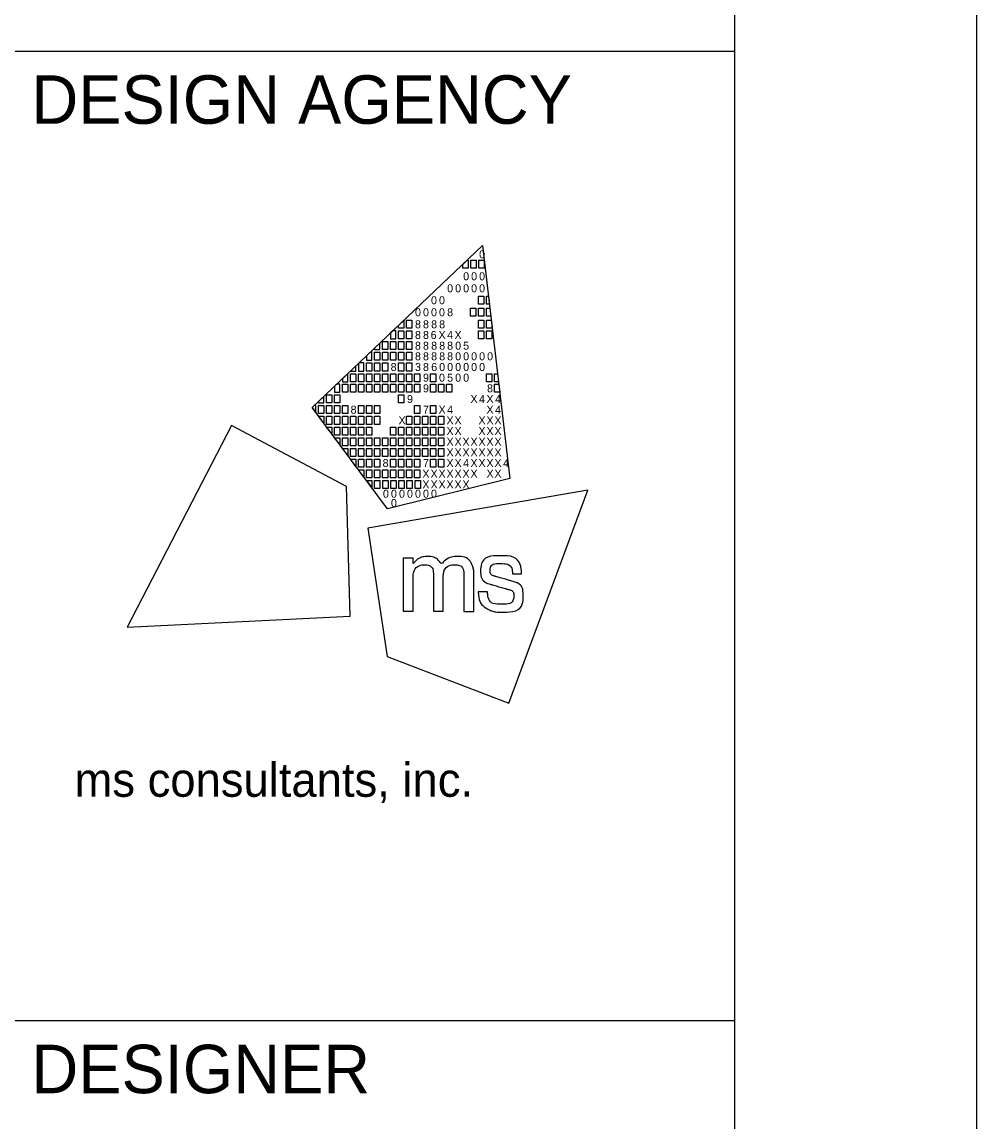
# Model space of a CAD drawing. Extents: x -0.2 to 33.8, y 0.1 to 22.1.
# Drawn here: x 31.828 to 33.798, y 2.411 to 4.681 of the extents above; entities that cross this region are included whole.
import ezdxf

# ---------------------------------------------------------------- set-up
doc = ezdxf.new("R2010")
doc.units = 0
for name, color, linetype in [('Default', 7, 'Continuous'), ('SH_Border', 7, 'Continuous'), ('SH_Cut_Line', 7, 'Continuous'), ('SH_Data', 7, 'Continuous')]:
    doc.layers.add(name, color=color, linetype=linetype)

msp = doc.modelspace()

# ---------------------------------------------------------------- linework, layer by layer
at = {"layer": 'Default'}
for p, q in [((32.4267, 3.8854), (32.778, 4.2196)), ((32.778, 4.2196), (32.778, 4.2196)), ((32.778, 4.2196), (32.8345, 3.7387)), ((32.5822, 3.6765), (32.4267, 3.8854)), ((32.8345, 3.7387), (32.5822, 3.6765))]:
    msp.add_line(p, q, dxfattribs=at)
for points in [[(32.7371, 4.1807), (32.7461, 4.1893), (32.7481, 4.1893), (32.7481, 4.1728), (32.7371, 4.1728)], [(32.7536, 4.1893), (32.7646, 4.1893), (32.7646, 4.1728), (32.7536, 4.1728)], [(32.7701, 4.1893), (32.7811, 4.1893), (32.7811, 4.1728), (32.7701, 4.1728)], [(32.7698, 4.115), (32.7808, 4.115), (32.7808, 4.0985), (32.7698, 4.0985)], [(32.7863, 4.115), (32.7903, 4.115), (32.7922, 4.0985), (32.7863, 4.0985)], [(32.7533, 4.0902), (32.7643, 4.0902), (32.7643, 4.0737), (32.7533, 4.0737)], [(32.7698, 4.0902), (32.7808, 4.0902), (32.7808, 4.0737), (32.7698, 4.0737)], [(32.7863, 4.0902), (32.7932, 4.0902), (32.7951, 4.0737), (32.7863, 4.0737)], [(32.6045, 4.0546), (32.6156, 4.0651), (32.6156, 4.0489), (32.6045, 4.0489)], [(32.6215, 4.0654), (32.6325, 4.0654), (32.6325, 4.0489), (32.6215, 4.0489)], [(32.7698, 4.0654), (32.7808, 4.0654), (32.7808, 4.0489), (32.7698, 4.0489)], [(32.7863, 4.0654), (32.7961, 4.0654), (32.7973, 4.0553), (32.7973, 4.0489), (32.7863, 4.0489)], [(32.605, 4.0434), (32.616, 4.0434), (32.616, 4.0269), (32.605, 4.0269)], [(32.6215, 4.0434), (32.6325, 4.0434), (32.6325, 4.0269), (32.6215, 4.0269)], [(32.7698, 4.0434), (32.7808, 4.0434), (32.7808, 4.0269), (32.7698, 4.0269)], [(32.7863, 4.0434), (32.7973, 4.0434), (32.7973, 4.0269), (32.7863, 4.0269)], [(32.5719, 4.0214), (32.5829, 4.0214), (32.5829, 4.0049), (32.5719, 4.0049)], [(32.5885, 4.0214), (32.5995, 4.0214), (32.5995, 4.0049), (32.5885, 4.0049)], [(32.605, 4.0214), (32.616, 4.0214), (32.616, 4.0049), (32.605, 4.0049)], [(32.6215, 4.0214), (32.6325, 4.0214), (32.6325, 4.0049), (32.6215, 4.0049)], [(32.5554, 3.9994), (32.5664, 3.9994), (32.5664, 3.9829), (32.5554, 3.9829)], [(32.5719, 3.9994), (32.5829, 3.9994), (32.5829, 3.9829), (32.5719, 3.9829)], [(32.5885, 3.9994), (32.5995, 3.9994), (32.5995, 3.9829), (32.5885, 3.9829)], [(32.605, 3.9994), (32.616, 3.9994), (32.616, 3.9829), (32.605, 3.9829)], [(32.6215, 3.9994), (32.6325, 3.9994), (32.6325, 3.9829), (32.6215, 3.9829)], [(32.5389, 3.9774), (32.5499, 3.9774), (32.5499, 3.9608), (32.5389, 3.9608)], [(32.5554, 3.9774), (32.5664, 3.9774), (32.5664, 3.9608), (32.5554, 3.9608)], [(32.5719, 3.9774), (32.5829, 3.9774), (32.5829, 3.9608), (32.5719, 3.9608)], [(32.605, 3.9774), (32.616, 3.9774), (32.616, 3.9608), (32.605, 3.9608)], [(32.6215, 3.9774), (32.6325, 3.9774), (32.6325, 3.9608), (32.6215, 3.9608)], [(32.5059, 3.9553), (32.5169, 3.9553), (32.5169, 3.9388), (32.5059, 3.9388)], [(32.5224, 3.9553), (32.5334, 3.9553), (32.5334, 3.9388), (32.5224, 3.9388)], [(32.5389, 3.9553), (32.5499, 3.9553), (32.5499, 3.9388), (32.5389, 3.9388)], [(32.5554, 3.9553), (32.5664, 3.9553), (32.5664, 3.9388), (32.5554, 3.9388)], [(32.5719, 3.9553), (32.5829, 3.9553), (32.5829, 3.9388), (32.5719, 3.9388)], [(32.5885, 3.9553), (32.5995, 3.9553), (32.5995, 3.9388), (32.5885, 3.9388)], [(32.605, 3.9553), (32.616, 3.9553), (32.616, 3.9388), (32.605, 3.9388)], [(32.6215, 3.9553), (32.6325, 3.9553), (32.6325, 3.9388), (32.6215, 3.9388)], [(32.638, 3.9553), (32.649, 3.9553), (32.649, 3.9388), (32.638, 3.9388)], [(32.671, 3.9553), (32.682, 3.9553), (32.682, 3.9388), (32.671, 3.9388)], [(32.7863, 3.9553), (32.7973, 3.9553), (32.7973, 3.9388), (32.7863, 3.9388)], [(32.8027, 3.9553), (32.809, 3.9553), (32.811, 3.9388), (32.8027, 3.9388)], [(32.4894, 3.9333), (32.5004, 3.9333), (32.5004, 3.9168), (32.4894, 3.9168)], [(32.5059, 3.9333), (32.5169, 3.9333), (32.5169, 3.9168), (32.5059, 3.9168)], [(32.5224, 3.9333), (32.5334, 3.9333), (32.5334, 3.9168), (32.5224, 3.9168)], [(32.5389, 3.9333), (32.5499, 3.9333), (32.5499, 3.9168), (32.5389, 3.9168)], [(32.5554, 3.9333), (32.5664, 3.9333), (32.5664, 3.9168), (32.5554, 3.9168)], [(32.5719, 3.9333), (32.5829, 3.9333), (32.5829, 3.9168), (32.5719, 3.9168)], [(32.5885, 3.9333), (32.5995, 3.9333), (32.5995, 3.9168), (32.5885, 3.9168)], [(32.605, 3.9333), (32.616, 3.9333), (32.616, 3.9168), (32.605, 3.9168)], [(32.6215, 3.9333), (32.6325, 3.9333), (32.6325, 3.9168), (32.6215, 3.9168)], [(32.638, 3.9333), (32.649, 3.9333), (32.649, 3.9168), (32.638, 3.9168)], [(32.671, 3.9333), (32.682, 3.9333), (32.682, 3.9168), (32.671, 3.9168)], [(32.6875, 3.9333), (32.6985, 3.9333), (32.6985, 3.9168), (32.6875, 3.9168)], [(32.7039, 3.9333), (32.7149, 3.9333), (32.7149, 3.9168), (32.7039, 3.9168)], [(32.8027, 3.9333), (32.8116, 3.9333), (32.8136, 3.9168), (32.8027, 3.9168)], [(32.4563, 3.9113), (32.4674, 3.9113), (32.4674, 3.8948), (32.4563, 3.8948)], [(32.4729, 3.9113), (32.4839, 3.9113), (32.4839, 3.8948), (32.4729, 3.8948)], [(32.605, 3.9113), (32.616, 3.9113), (32.616, 3.8948), (32.605, 3.8948)], [(32.4398, 3.8893), (32.4508, 3.8893), (32.4508, 3.8728), (32.4398, 3.8728)], [(32.4563, 3.8893), (32.4674, 3.8893), (32.4674, 3.8728), (32.4563, 3.8728)], [(32.4729, 3.8893), (32.4839, 3.8893), (32.4839, 3.8728), (32.4729, 3.8728)], [(32.4894, 3.8893), (32.5004, 3.8893), (32.5004, 3.8728), (32.4894, 3.8728)], [(32.5224, 3.8893), (32.5334, 3.8893), (32.5334, 3.8728), (32.5224, 3.8728)], [(32.5389, 3.8893), (32.5499, 3.8893), (32.5499, 3.8728), (32.5389, 3.8728)], [(32.5554, 3.8893), (32.5664, 3.8893), (32.5664, 3.8728), (32.5554, 3.8728)], [(32.638, 3.8893), (32.649, 3.8893), (32.649, 3.8728), (32.638, 3.8728)], [(32.671, 3.8893), (32.682, 3.8893), (32.682, 3.8728), (32.671, 3.8728)], [(32.4398, 3.8673), (32.4508, 3.8673), (32.4508, 3.8535)], [(32.4563, 3.8673), (32.4674, 3.8673), (32.4674, 3.8507), (32.4563, 3.8507)], [(32.4729, 3.8673), (32.4839, 3.8673), (32.4839, 3.8507), (32.4729, 3.8507)], [(32.4894, 3.8673), (32.5004, 3.8673), (32.5004, 3.8507), (32.4894, 3.8507)], [(32.5059, 3.8673), (32.5169, 3.8673), (32.5169, 3.8507), (32.5059, 3.8507)], [(32.5224, 3.8673), (32.5334, 3.8673), (32.5334, 3.8507), (32.5224, 3.8507)], [(32.5389, 3.8673), (32.5499, 3.8673), (32.5499, 3.8507), (32.5389, 3.8507)], [(32.5554, 3.8673), (32.5664, 3.8673), (32.5664, 3.8507), (32.5554, 3.8507)], [(32.6215, 3.8673), (32.6325, 3.8673), (32.6325, 3.8507), (32.6215, 3.8507)], [(32.638, 3.8673), (32.649, 3.8673), (32.649, 3.8507), (32.638, 3.8507)], [(32.6545, 3.8673), (32.6655, 3.8673), (32.6655, 3.8507), (32.6545, 3.8507)], [(32.671, 3.8673), (32.682, 3.8673), (32.682, 3.8507), (32.671, 3.8507)], [(32.6875, 3.8673), (32.6985, 3.8673), (32.6985, 3.8507), (32.6875, 3.8507)], [(32.4563, 3.8452), (32.4674, 3.8452), (32.4674, 3.8315)], [(32.4729, 3.8452), (32.4839, 3.8452), (32.4839, 3.8287), (32.4729, 3.8287)], [(32.4894, 3.8452), (32.5004, 3.8452), (32.5004, 3.8287), (32.4894, 3.8287)], [(32.5059, 3.8452), (32.5169, 3.8452), (32.5169, 3.8287), (32.5059, 3.8287)], [(32.5224, 3.8452), (32.5334, 3.8452), (32.5334, 3.8287), (32.5224, 3.8287)], [(32.5389, 3.8452), (32.5499, 3.8452), (32.5499, 3.8287), (32.5389, 3.8287)], [(32.5885, 3.8452), (32.5995, 3.8452), (32.5995, 3.8287), (32.5885, 3.8287)], [(32.605, 3.8452), (32.616, 3.8452), (32.616, 3.8287), (32.605, 3.8287)], [(32.6215, 3.8452), (32.6325, 3.8452), (32.6325, 3.8287), (32.6215, 3.8287)], [(32.638, 3.8452), (32.649, 3.8452), (32.649, 3.8287), (32.638, 3.8287)], [(32.6545, 3.8452), (32.6655, 3.8452), (32.6655, 3.8287), (32.6545, 3.8287)], [(32.671, 3.8452), (32.682, 3.8452), (32.682, 3.8287), (32.671, 3.8287)], [(32.6875, 3.8452), (32.6985, 3.8452), (32.6985, 3.8287), (32.6875, 3.8287)], [(32.4729, 3.8232), (32.4839, 3.8232), (32.4839, 3.8095)], [(32.4839, 3.8232), (32.4839, 3.8232), (32.4839, 3.8232)], [(32.4894, 3.8232), (32.5004, 3.8232), (32.5004, 3.8067), (32.4894, 3.8067)], [(32.5059, 3.8232), (32.5169, 3.8232), (32.5169, 3.8067), (32.5059, 3.8067)], [(32.5224, 3.8232), (32.5334, 3.8232), (32.5334, 3.8067), (32.5224, 3.8067)], [(32.5389, 3.8232), (32.5499, 3.8232), (32.5499, 3.8067), (32.5389, 3.8067)], [(32.5554, 3.8232), (32.5664, 3.8232), (32.5664, 3.8067), (32.5554, 3.8067)], [(32.5719, 3.8232), (32.5829, 3.8232), (32.5829, 3.8067), (32.5719, 3.8067)], [(32.5885, 3.8232), (32.5995, 3.8232), (32.5995, 3.8067), (32.5885, 3.8067)], [(32.605, 3.8232), (32.616, 3.8232), (32.616, 3.8067), (32.605, 3.8067)], [(32.6215, 3.8232), (32.6325, 3.8232), (32.6325, 3.8067), (32.6215, 3.8067)], [(32.638, 3.8232), (32.649, 3.8232), (32.649, 3.8067), (32.638, 3.8067)], [(32.6545, 3.8232), (32.6655, 3.8232), (32.6655, 3.8067), (32.6545, 3.8067)], [(32.671, 3.8232), (32.682, 3.8232), (32.682, 3.8067), (32.671, 3.8067)], [(32.6875, 3.8232), (32.6985, 3.8232), (32.6985, 3.8067), (32.6875, 3.8067)], [(32.4894, 3.8012), (32.5004, 3.8012), (32.5004, 3.7874)], [(32.5059, 3.8012), (32.5169, 3.8012), (32.5169, 3.7847), (32.5059, 3.7847)], [(32.5224, 3.8012), (32.5334, 3.8012), (32.5334, 3.7847), (32.5224, 3.7847)], [(32.5389, 3.8012), (32.5499, 3.8012), (32.5499, 3.7847), (32.5389, 3.7847)], [(32.5554, 3.8012), (32.5664, 3.8012), (32.5664, 3.7847), (32.5554, 3.7847)], [(32.5719, 3.8012), (32.5829, 3.8012), (32.5829, 3.7847), (32.5719, 3.7847)], [(32.5885, 3.8012), (32.5995, 3.8012), (32.5995, 3.7847), (32.5885, 3.7847)], [(32.605, 3.8012), (32.616, 3.8012), (32.616, 3.7847), (32.605, 3.7847)], [(32.6215, 3.8012), (32.6325, 3.8012), (32.6325, 3.7847), (32.6215, 3.7847)], [(32.638, 3.8012), (32.649, 3.8012), (32.649, 3.7847), (32.638, 3.7847)], [(32.6545, 3.8012), (32.6655, 3.8012), (32.6655, 3.7847), (32.6545, 3.7847)], [(32.671, 3.8012), (32.682, 3.8012), (32.682, 3.7847), (32.671, 3.7847)], [(32.6875, 3.8012), (32.6985, 3.8012), (32.6985, 3.7847), (32.6875, 3.7847)], [(32.5169, 3.764), (32.5057, 3.7792), (32.5169, 3.7792)], [(32.5224, 3.7792), (32.5334, 3.7792), (32.5334, 3.7627), (32.5224, 3.7627)], [(32.5389, 3.7792), (32.5499, 3.7792), (32.5499, 3.7627), (32.5389, 3.7627)], [(32.5554, 3.7792), (32.5664, 3.7792), (32.5664, 3.7627), (32.5554, 3.7627)], [(32.5885, 3.7792), (32.5995, 3.7792), (32.5995, 3.7627), (32.5885, 3.7627)], [(32.605, 3.7792), (32.616, 3.7792), (32.616, 3.7627), (32.605, 3.7627)], [(32.6215, 3.7792), (32.6325, 3.7792), (32.6325, 3.7627), (32.6215, 3.7627)], [(32.638, 3.7792), (32.649, 3.7792), (32.649, 3.7627), (32.638, 3.7627)], [(32.671, 3.7792), (32.682, 3.7792), (32.682, 3.7627), (32.671, 3.7627)], [(32.6875, 3.7792), (32.6985, 3.7792), (32.6985, 3.7627), (32.6875, 3.7627)], [(32.5332, 3.7417), (32.5224, 3.7572), (32.5334, 3.7572)], [(32.5389, 3.7572), (32.5499, 3.7572), (32.5499, 3.7407), (32.5389, 3.7407)], [(32.5554, 3.7572), (32.5664, 3.7572), (32.5664, 3.7407), (32.5554, 3.7407)], [(32.5719, 3.7572), (32.5829, 3.7572), (32.5829, 3.7407), (32.5719, 3.7407)], [(32.5885, 3.7572), (32.5995, 3.7572), (32.5995, 3.7407), (32.5885, 3.7407)], [(32.605, 3.7572), (32.616, 3.7572), (32.616, 3.7407), (32.605, 3.7407)], [(32.6215, 3.7572), (32.6325, 3.7572), (32.6325, 3.7407), (32.6215, 3.7407)], [(32.638, 3.7572), (32.649, 3.7572), (32.649, 3.7407), (32.638, 3.7407)], [(32.5394, 3.7352), (32.5499, 3.7352), (32.55, 3.721)], [(32.5555, 3.7352), (32.5665, 3.7352), (32.5665, 3.7187), (32.5555, 3.7187)], [(32.5722, 3.7352), (32.5832, 3.7352), (32.5832, 3.7187), (32.5722, 3.7187)], [(32.5886, 3.7352), (32.5996, 3.7352), (32.5996, 3.7187), (32.5886, 3.7187)], [(32.6052, 3.7352), (32.6162, 3.7352), (32.6162, 3.7187), (32.6052, 3.7187)], [(32.6221, 3.7351), (32.6331, 3.7351), (32.6331, 3.7186), (32.6221, 3.7186)], [(32.6388, 3.7351), (32.6498, 3.7351), (32.6498, 3.7186), (32.6388, 3.7186)]]:
    msp.add_lwpolyline(points, close=True, dxfattribs=at)
for points in [[(32.5995, 4.0434), (32.5928, 4.0434), (32.5885, 4.0393), (32.5885, 4.0269), (32.5995, 4.0269), (32.5995, 4.0434)], [(32.5664, 4.0183), (32.5554, 4.0079), (32.5554, 4.0049), (32.5664, 4.0049), (32.5664, 4.0183)], [(32.5499, 4.0026), (32.5389, 3.9922), (32.5389, 3.9829), (32.5499, 3.9829), (32.5499, 4.0026)], [(32.5334, 3.9774), (32.5233, 3.9774), (32.5224, 3.9764), (32.5224, 3.9608), (32.5334, 3.9608), (32.5334, 3.9774)], [(32.5004, 3.9555), (32.4894, 3.945), (32.4894, 3.9388), (32.5004, 3.9388), (32.5004, 3.9555)], [(32.5169, 3.9712), (32.506, 3.9608), (32.5169, 3.9608), (32.5169, 3.9712)], [(32.4839, 3.9333), (32.4771, 3.9333), (32.4729, 3.9293), (32.4729, 3.9168), (32.4839, 3.9168), (32.4839, 3.9333)], [(32.4508, 3.9084), (32.4398, 3.8979), (32.4398, 3.8948), (32.4508, 3.8948), (32.4508, 3.9084)], [(32.4343, 3.8893), (32.4308, 3.8893), (32.4267, 3.8854), (32.4343, 3.8752), (32.4343, 3.8893)], [(32.2604, 3.8484), (32.0451, 3.4323), (32.5048, 3.455), (32.4976, 3.7227), (32.2604, 3.8484)], [(32.8321, 3.2757), (32.9951, 3.7149), (32.5416, 3.6364), (32.5814, 3.3716), (32.8321, 3.2757)]]:
    msp.add_lwpolyline(points, dxfattribs=at)
for points in [[(32.614, 3.465), (32.614, 3.465), (32.614, 3.5744), (32.614, 3.5744), (32.614, 3.5744), (32.6347, 3.5744), (32.6347, 3.5744), (32.6347, 3.5744), (32.6347, 3.5632), (32.6347, 3.5632), (32.6438, 3.5734), (32.6549, 3.578), (32.6647, 3.578), (32.678, 3.578), (32.6883, 3.5707), (32.6929, 3.5601), (32.7007, 3.5716), (32.7142, 3.5781), (32.7258, 3.5781), (32.7417, 3.5781), (32.7543, 3.5685), (32.7586, 3.5548), (32.7586, 3.5547), (32.7586, 3.5547), (32.7586, 3.5546), (32.7593, 3.5525), (32.7598, 3.5507), (32.7598, 3.5406), (32.7598, 3.5406), (32.7598, 3.4649), (32.7598, 3.4649), (32.7598, 3.4649), (32.7395, 3.4649), (32.7395, 3.4649), (32.7395, 3.4649), (32.7395, 3.5383), (32.7395, 3.5383), (32.7395, 3.5536), (32.7311, 3.5609), (32.7202, 3.5609), (32.7087, 3.5609), (32.6971, 3.5505), (32.6971, 3.5336), (32.6971, 3.5336), (32.6971, 3.465), (32.6971, 3.465), (32.6971, 3.465), (32.6766, 3.465), (32.6766, 3.465), (32.6766, 3.465), (32.6766, 3.5394), (32.6766, 3.5394), (32.6766, 3.5538), (32.668, 3.5609), (32.6588, 3.5609), (32.6476, 3.5609), (32.6346, 3.5505), (32.6346, 3.5297), (32.6346, 3.5297), (32.6346, 3.465), (32.6346, 3.465), (32.6346, 3.465), (32.614, 3.465), (32.614, 3.465)], [(32.7687, 3.5043), (32.7687, 3.5043), (32.7687, 3.5052), (32.7687, 3.5052), (32.7687, 3.5052), (32.7695, 3.5052), (32.7695, 3.5052), (32.7695, 3.5052), (32.7875, 3.5052), (32.7875, 3.5052), (32.7875, 3.5052), (32.7881, 3.5052), (32.7881, 3.5052), (32.7881, 3.5052), (32.7882, 3.5045), (32.7882, 3.5045), (32.7895, 3.4889), (32.7979, 3.4795), (32.8182, 3.4795), (32.8365, 3.4795), (32.8425, 3.4889), (32.8425, 3.4966), (32.8425, 3.5067), (32.8348, 3.5093), (32.8267, 3.5115), (32.8267, 3.5115), (32.7962, 3.5202), (32.7962, 3.5202), (32.7812, 3.5244), (32.774, 3.5354), (32.774, 3.5477), (32.774, 3.5638), (32.786, 3.5797), (32.8144, 3.5797), (32.844, 3.5797), (32.8581, 3.562), (32.8581, 3.543), (32.8581, 3.543), (32.8581, 3.5422), (32.8581, 3.5422), (32.8581, 3.5422), (32.8574, 3.5422), (32.8574, 3.5422), (32.8574, 3.5422), (32.8404, 3.5422), (32.8404, 3.5422), (32.8404, 3.5422), (32.8397, 3.5422), (32.8397, 3.5422), (32.8397, 3.5422), (32.8397, 3.5429), (32.8397, 3.5429), (32.8393, 3.5543), (32.8318, 3.5635), (32.8148, 3.5635), (32.7983, 3.5635), (32.7935, 3.5553), (32.7935, 3.5492), (32.7935, 3.5443), (32.7961, 3.5394), (32.8051, 3.5368), (32.8051, 3.5368), (32.8347, 3.5283), (32.8347, 3.5283), (32.8554, 3.5224), (32.8619, 3.5112), (32.8619, 3.4974), (32.8619, 3.4797), (32.8502, 3.4633), (32.8179, 3.4633), (32.8044, 3.4633), (32.7969, 3.4656), (32.7915, 3.4683), (32.7782, 3.4749), (32.7701, 3.4871), (32.7687, 3.5043)]]:
    msp.add_open_spline(points, degree=3, dxfattribs=at)
at = {"layer": 'SH_Border'}
for p, q in [((31.7977, 4.6208), (33.2977, 4.6208)), ((31.7977, 2.6208), (33.2977, 2.6208))]:
    msp.add_line(p, q, dxfattribs=at)
msp.add_lwpolyline([(1.2977, 21.6208), (33.2977, 21.6208), (33.2977, 0.6208), (1.2977, 0.6208)], close=True, dxfattribs=at)
at = {"layer": 'SH_Cut_Line'}
msp.add_lwpolyline([(-0.2023, 0.1208), (33.7977, 0.1208), (33.7977, 22.1208), (-0.2023, 22.1208)], close=True, dxfattribs=at)
at = {"layer": 'SH_Data'}
msp.add_line((32.5477, 3.6208), (32.5477, 3.6208), dxfattribs=at)

# ---------------------------------------------------------------- texts
at = {"layer": 'Default'}
for s, p in [('0', (32.7709, 4.1932)), ('0', (32.738, 4.148)), ('0', (32.7544, 4.148)), ('0', (32.7709, 4.148)), ('0', (32.705, 4.1232)), ('0', (32.7215, 4.1232)), ('0', (32.738, 4.1232)), ('0', (32.7544, 4.1232)), ('0', (32.7709, 4.1232)), ('0', (32.6717, 4.0985)), ('0', (32.6882, 4.0985)), ('0', (32.6387, 4.0737)), ('0', (32.6552, 4.0737)), ('0', (32.6717, 4.0737)), ('0', (32.6882, 4.0737)), ('8', (32.705, 4.0737)), ('8', (32.6387, 4.0489)), ('8', (32.6552, 4.0489)), ('8', (32.672, 4.0489)), ('8', (32.6885, 4.0489)), ('8', (32.6387, 4.0269)), ('8', (32.6552, 4.0269)), ('6', (32.671, 4.0269)), ('X', (32.6873, 4.0269)), ('4', (32.705, 4.0269)), ('X', (32.7202, 4.0269)), ('8', (32.6387, 4.0048)), ('8', (32.6552, 4.0048)), ('8', (32.672, 4.0048)), ('8', (32.6886, 4.0048)), ('8', (32.705, 4.0048)), ('0', (32.7215, 4.0048)), ('5', (32.7379, 4.0048)), ('8', (32.6387, 3.9829)), ('8', (32.6552, 3.9829)), ('8', (32.672, 3.9829)), ('8', (32.6886, 3.9829)), ('8', (32.705, 3.9829)), ('0', (32.7215, 3.9829)), ('0', (32.738, 3.9829)), ('0', (32.7544, 3.9829)), ('0', (32.7709, 3.9829)), ('0', (32.7874, 3.9829)), ('8', (32.5885, 3.9608)), ('3', (32.6387, 3.9608)), ('8', (32.6552, 3.9608)), ('6', (32.6721, 3.9608)), ('0', (32.6885, 3.9608)), ('0', (32.705, 3.9608)), ('0', (32.7215, 3.9608)), ('0', (32.738, 3.9608)), ('0', (32.7544, 3.9608)), ('0', (32.7709, 3.9608)), ('9', (32.6552, 3.9388)), ('0', (32.6882, 3.9388)), ('5', (32.7049, 3.9388)), ('0', (32.7215, 3.9388)), ('0', (32.738, 3.9388)), ('9', (32.6552, 3.9168)), ('8', (32.7873, 3.9168)), ('9', (32.6222, 3.8948)), ('X', (32.7531, 3.8948)), ('4', (32.7709, 3.8948)), ('X', (32.7861, 3.8948)), ('4', (32.8038, 3.8948)), ('8', (32.5059, 3.8728)), ('7', (32.6552, 3.8728)), ('X', (32.6873, 3.8728)), ('4', (32.705, 3.8728)), ('X', (32.7861, 3.8728)), ('4', (32.8038, 3.8728)), ('X', (32.6047, 3.8507)), ('X', (32.7037, 3.8507)), ('X', (32.7202, 3.8507)), ('X', (32.7696, 3.8507)), ('X', (32.7861, 3.8507)), ('X', (32.8025, 3.8507)), ('X', (32.7037, 3.8287)), ('X', (32.7202, 3.8287)), ('X', (32.7696, 3.8287)), ('X', (32.7861, 3.8287)), ('X', (32.8025, 3.8287)), ('X', (32.7037, 3.8067)), ('X', (32.7202, 3.8067)), ('X', (32.7366, 3.8067)), ('X', (32.7531, 3.8067)), ('X', (32.7696, 3.8067)), ('X', (32.7861, 3.8067)), ('X', (32.8025, 3.8067)), ('X', (32.7037, 3.7847)), ('X', (32.7202, 3.7847)), ('X', (32.7366, 3.7847)), ('X', (32.7531, 3.7847)), ('X', (32.7696, 3.7847)), ('X', (32.7861, 3.7847)), ('X', (32.8025, 3.7847)), ('8', (32.5719, 3.7627)), ('7', (32.6552, 3.7627)), ('X', (32.7037, 3.7627)), ('X', (32.7202, 3.7627)), ('4', (32.738, 3.7627)), ('X', (32.7531, 3.7627)), ('X', (32.7696, 3.7627)), ('X', (32.7861, 3.7627)), ('X', (32.8025, 3.7627)), ('4', (32.8203, 3.7627)), ('X', (32.6539, 3.7407)), ('X', (32.6708, 3.7407)), ('X', (32.6872, 3.7407)), ('X', (32.7037, 3.7407)), ('X', (32.7202, 3.7407)), ('X', (32.7366, 3.7407)), ('X', (32.7531, 3.7407)), ('X', (32.7863, 3.7407)), ('X', (32.8025, 3.7407)), ('X', (32.6539, 3.7186)), ('X', (32.6708, 3.7186)), ('X', (32.6872, 3.7186)), ('X', (32.7037, 3.7186)), ('X', (32.7202, 3.7186)), ('X', (32.7366, 3.7186)), ('0', (32.5726, 3.6994)), ('0', (32.5891, 3.6994)), ('0', (32.6057, 3.6994)), ('0', (32.6222, 3.6994)), ('0', (32.6387, 3.6994)), ('0', (32.6552, 3.6994)), ('0', (32.6717, 3.6994)), ('0', (32.5891, 3.6802))]:
    msp.add_text(s, height=0.0165, rotation=360, dxfattribs=at).set_placement(p)
at = {"layer": 'SH_Border'}
msp.add_text('ms consultants, inc.', height=0.07, rotation=360, dxfattribs=at).set_placement((31.9365, 3.0824))
at = {"layer": 'SH_Data'}
for s, p in [('DESIGN AGENCY', (31.8477, 4.4708)), ('DESIGNER', (31.8477, 2.4708))]:
    msp.add_text(s, height=0.1, dxfattribs=at).set_placement(p)

doc.saveas('drawing.dxf')
